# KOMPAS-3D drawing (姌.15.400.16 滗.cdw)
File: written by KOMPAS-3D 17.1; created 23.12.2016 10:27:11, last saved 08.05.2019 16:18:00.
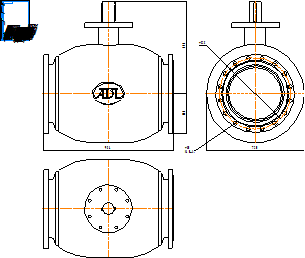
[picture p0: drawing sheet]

Sheet 1: A4, portrait

Title block, sheet 1: name: КШ.15.400.16 фф; material: Внимание! Данный продукт является объектом авторского права ООО «Торговый Дом АДЛ». / Запрещается изменение, копирование, распространение / (в том числе путем копирования на другие сайты и ресурсы в Интернете) / или любое иное использование информации и объектов без предварительного / согласия правообладателя (ООО «Торговый Дом АДЛ»).; sheets: 1; organisation: ООО "Торговый дом АДЛ"; sheet format: A4; stored path: C:\Users\tra\Desktop\2д чертежи\Шаровые краны БИВАЛ\КШ_Бивал_серия_14_15\KOMPAS_2D\КШ.15.400.16 фф.cdw

Views: Вид 1, Проекционный вид 2, Проекционный вид 3
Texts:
  Klimkovich
  ADL
Dimensions and other numbers on the sheet: 956; 673; 290; 720; 525; 30; 16 Отв.; 1:1; 1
